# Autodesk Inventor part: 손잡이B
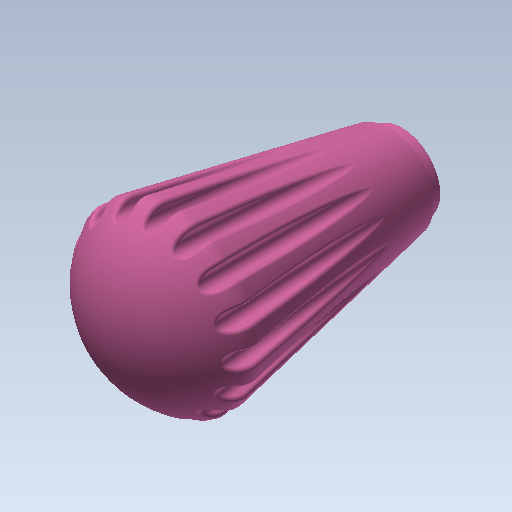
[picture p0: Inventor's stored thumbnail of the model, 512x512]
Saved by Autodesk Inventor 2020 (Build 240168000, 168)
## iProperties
Created: 2022-02
Part Number: 손잡이B
Material: ABS 플라스틱
Document SubType Name: Modeling
Designer: mdu-edu
Density: 1.06 g/cm^3
Mass: 11.327 g
Surface Area: 35.7237 cm^2
Volume: 10.6858 cm^3
Appearance: 분홍색
Author: mdu-edu
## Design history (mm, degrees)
sketch "스케치1"
  geometry: L1 (0, 0)-(6.5, 0); L2 (6.5, 0)-(12.649, 32); L3 (0, 0)-(0, 40); A1 r 14 centre (0, 26) between (12.649, 32) and (0, 40)
  constraints: 6 end point, 2 point on circle, 1 centre point, 1 horizontal, 1 perpendicular, 1 point on line
  dimensions: "d4" = 40 distance from line of L1 L3.end; "d5" = 13 diameter of L1.end L3; "d6" = 32 distance from line of L1 L2.end; "d7" = 14 radius of A1
revolve "회전1" sketch "스케치1" stored, may be unused: angle "d8" = 90 deg
fillet "모깎기1" dims "d9" = 3
sketch "스케치2"
  geometry: C1 r 5.5 at (0, 0); 1 further point
  constraints: 1 centre point, 1 coincident
  dimensions: "d24" = 11 diameter of C1
extrude "돌출1" join sketch "스케치2" distance "d26" = 2; taper "d27" = 0 deg
hole "구멍1" diameter "d17" = 6.647; stored, may be unused: countersink angle "d21" = 90 deg, drill point angle "d23" = 118 deg; dims "d18" = 14, "d19" = 4, "d20" = 2, "d22" = 16, "d46" = 10, "d47" = 10
fillet "모깎기2" dims "d30" = 1
sketch "스케치3"
  geometry: L1 (12.451, 30.97)-(6.5, 0) reference; L2 (8.037, 8)-(10.806, 34.901); L3 (-5.5, -2)-(5.5, -2) reference; A1 r 14 centre (0, 26) between (12.097, 33.046) and (-12.097, 33.046) reference; A2 r 3 centre (9.505, 31.536) between (12.451, 30.97) and (12.097, 33.046) reference; 1 further point
  constraints: 2 end point, 1 point on circle, 1 point on line
  dimensions: "d31" = 5 deg angle of L1 L2; "d32" = 10 distance from line of L3 L2.start
extrude "돌출2" cut sketch "스케치3" stored distance "d33" = 2; taper "d34" = 0 deg
fillet "모깎기3" dims "d35" = 1
fillet "모깎기4" dims "d36" = 0.5
node "솔리드1"
pattern_circular "원형 패턴1" dims angle "d38" = 360 deg
